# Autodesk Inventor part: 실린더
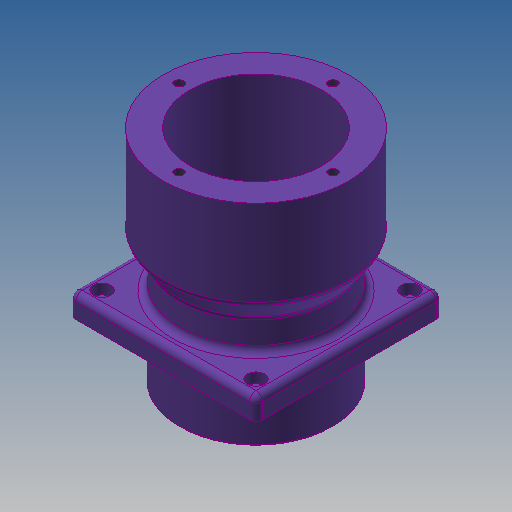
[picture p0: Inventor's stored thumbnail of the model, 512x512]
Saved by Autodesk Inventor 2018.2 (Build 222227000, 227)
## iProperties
Created: 2016-11
Part Number: 실린더
Material: 알루미늄 6061
Document SubType Name: Modeling
Designer: mduedu
Density: 2.71 g/cm^3
Mass: 568.286 g
Surface Area: 557.364 cm^2
Volume: 209.7 cm^3
Appearance: 보라색
Author: mduedu
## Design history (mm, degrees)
sketch "스케치1"
  geometry: L1 (0, 0)-(0, 101); L2 (30, 0)-(30, 101); L3 (30, 101)-(42, 101); L4 (42, 101)-(42, 61); L5 (42, 61)-(35, 51); L6 (35, 51)-(35, 0); L7 (35, 0)-(30, 0)
  constraints: 14 end point, 4 parallel, 2 horizontal alignment, 1 perpendicular, 1 vertical
  dimensions: "d0" = 101 distance of L1.start L1.end; "d1" = 60 diameter of L2.end L1; "d2" = 84 diameter of L3.end L1; "d3" = 70 diameter of L6.end L1; "d4" = 40 distance of L3.end L4.end; "d5" = 50 vertical distance of L5.end L3.end
revolve "회전1" sketch "스케치1" stored, may be unused: angle "d6" = 90 deg
node "작업 평면1"
sketch "스케치2"
  geometry: L1 (-42.5, -42.5)-(42.5, -42.5); L2 (42.5, -42.5)-(42.5, 42.5); L3 (42.5, 42.5)-(-42.5, 42.5); L4 (-42.5, 42.5)-(-42.5, -42.5); L5 (-42.5, -42.5)-(42.5, 42.5); L6 (42.5, -42.5)-(-42.5, 42.5); C1 r 35 at (0, 0) reference; C2 r 35 at (0, 0); 1 further point
  constraints: 12 end point, 2 midpoint, 2 parallel, 2 perpendicular, 1 centre point, 1 coincident, 1 concentric, 1 horizontal
  dimensions: "d8" = 85 distance of L2.end L3.end
extrude "돌출1" join sketch "스케치2" distance "d10" = 10; taper "d11" = 0 deg
fillet "모깎기1" dims "d12" = 3
fillet "모깎기2" dims "d13" = 3
chamfer "모따기1" distance "d14" = 1; stored, may be unused: second distance "d15" = 2, angle "d16" = 45 deg
chamfer "모따기2" distance "d17" = 5; stored, may be unused: second distance "d18" = 2, angle "d19" = 15 deg
sketch "스케치3"
  geometry: L1 (-35, -35)-(35, -35); L2 (35, -35)-(35, 35); L3 (35, 35)-(-35, 35); L4 (-35, 35)-(-35, -35); L5 (-35, -35)-(35, 35); L6 (35, -35)-(-35, 35); 5 further points
  constraints: 12 end point, 4 coincident, 2 midpoint, 2 parallel, 1 horizontal, 1 perpendicular
  dimensions: "d20" = 70 distance of L3.end L2.end; "d21" = 70 distance of L2.end L1.end
sketch "스케치4"
  geometry: 4 further points
  constraints: 4 other
hole "구멍1" sketch "스케치4" at (-35, 35), (35, 35), (35, -35), (-35, -35) diameter "d22" = 4.5; stored, may be unused: countersink angle "d26" = 90 deg, drill point angle "d28" = 0 deg; dims "d23" = 6, "d24" = 8, "d25" = 4.6, "d27" = 8
sketch "스케치5"
  geometry: 4 further points
  constraints: 4 other
hole "구멍2" sketch "스케치5" at (0, -35), (35, 0), (-35, 0), (0, 35) diameter "d29" = 4.134; stored, may be unused: countersink angle "d33" = 90 deg, drill point angle "d35" = 120 deg; dims "d30" = 12, "d31" = 4, "d32" = 2, "d34" = 15
node "솔리드1"
other parameters: "d7" = -27
